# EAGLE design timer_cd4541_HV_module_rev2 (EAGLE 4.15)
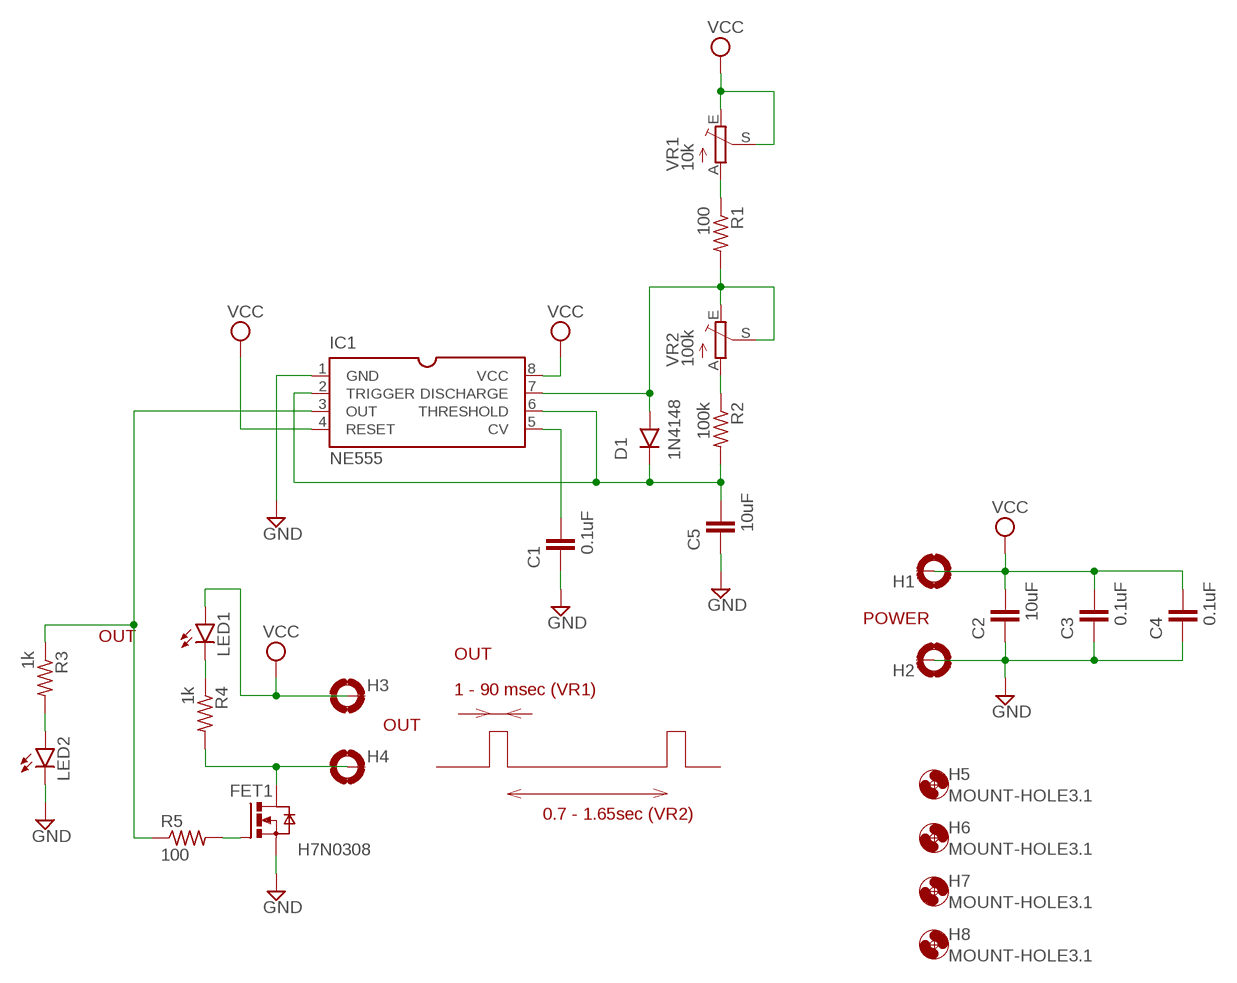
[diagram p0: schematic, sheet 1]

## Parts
C1  0.1uF  C-EU025-024X044_OLMX  [C025-024X044_OLMX]
C2  10uF  C-EU050-024X044_OLMX  [C050-024X044_OLMX]
C3  0.1uF  C-EU025-024X044_OLMX  [C025-024X044_OLMX]
C4  0.1uF  C-EU025-024X044_OLMX  [C025-024X044_OLMX]
C5  10uF  C-EU050-024X044_OLMX  [C050-024X044_OLMX]
D1  1N4148  DIODE  [DIODE]
FET1  H7N0308  IRF512HV  [TO-220HV]
H1  MOUNT-PAD-ROUND3.0-NOLING  [3,0-PAD-NOLING]
H2  MOUNT-PAD-ROUND3.0-NOLING  [3,0-PAD-NOLING]
H3  MOUNT-PAD-ROUND3.0-NOLING  [3,0-PAD-NOLING]
H4  MOUNT-PAD-ROUND3.0-NOLING  [3,0-PAD-NOLING]
H5  MOUNT-HOLE3.1  [3.1-HOLL]
H6  MOUNT-HOLE3.1  [3.1-HOLL]
H7  MOUNT-HOLE3.1  [3.1-HOLL]
H8  MOUNT-HOLE3.1  [3.1-HOLL]
IC1  NE555  [DIL8]
LED1  LED5MM_OLMX  [LED5MM_OLMX]
LED2  LED5MM_OLMX  [LED5MM_OLMX]
R1  100  R-US_0204/5_OLMX  [0204/5_OLMX]
R2  100k  R-US_0204/5_OLMX  [0204/5_OLMX]
R3  1k  R-US_0204/5_OLMX  [0204/5_OLMX]
R4  1k  R-US_0204/5_OLMX  [0204/5_OLMX]
R5  100  R-US_0204/5_OLMX  [0204/5_OLMX]
VR1  10k  TRIM_EU-B25P_OLMX  [B25P_OLMX]
VR2  100k  TRIM_EU-B25P_OLMX  [B25P_OLMX]

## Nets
GND [power]: C1.1 C2.1 C3.1 C4.1 C5.1 FET1.3(S) H2.B3,0(MOUNT) IC1.1(GND) LED2.K(C)
N$1: R2.1 VR2.A
N$4: R1.1 VR1.A
N$7: LED1.K(C) R4.1
N$8: C5.2 D1.K IC1.2(TRIGGER) IC1.6(THRESHOLD) R2.2
N$9: LED2.A R3.2
N$14: D1.A IC1.7(DISCHARGE) R1.2 VR2.E VR2.S
N$15: IC1.3(OUT) R3.1 R5.1
N$16: C1.2 IC1.5(CV)
N$19: FET1.1(G) R5.2
OUT-: FET1.2(D) H4.B3,0(MOUNT) R4.2
VCC [power]: C2.2 C3.2 C4.2 H1.B3,0(MOUNT) H3.B3,0(MOUNT) IC1.4(RESET) IC1.8(VCC) LED1.A VR1.E VR1.S

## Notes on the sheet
- POWER
- OUT
- OUT
- 1 - 90 msec (VR1)
- OUT
- 0.7 - 1.65sec (VR2)

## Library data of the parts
C1-C5 = rcl:C-EU: CAPACITOR, European symbol
D1 = 001mylib:DIODE
FET1 = transistor-power:IRF512: N-CHANNEL MOS FET
H1-H4 = holes:MOUNT-PAD-ROUND: MOUNTING PAD, round
H5-H8 = holes:MOUNT-HOLE: MOUNTING HOLE with drill center marker
IC1 = 001mylib:NE555
LED1 LED2 = led:LED: LED
R1-R5 = rcl:R-US_: RESISTOR, American symbol
VR1 VR2 = pot:TRIM_EU-: POTENTIOMETER

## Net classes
0 default: width 0.508 mm, drill 0.406 mm
1 power: width 0.635 mm, drill 0.508 mm

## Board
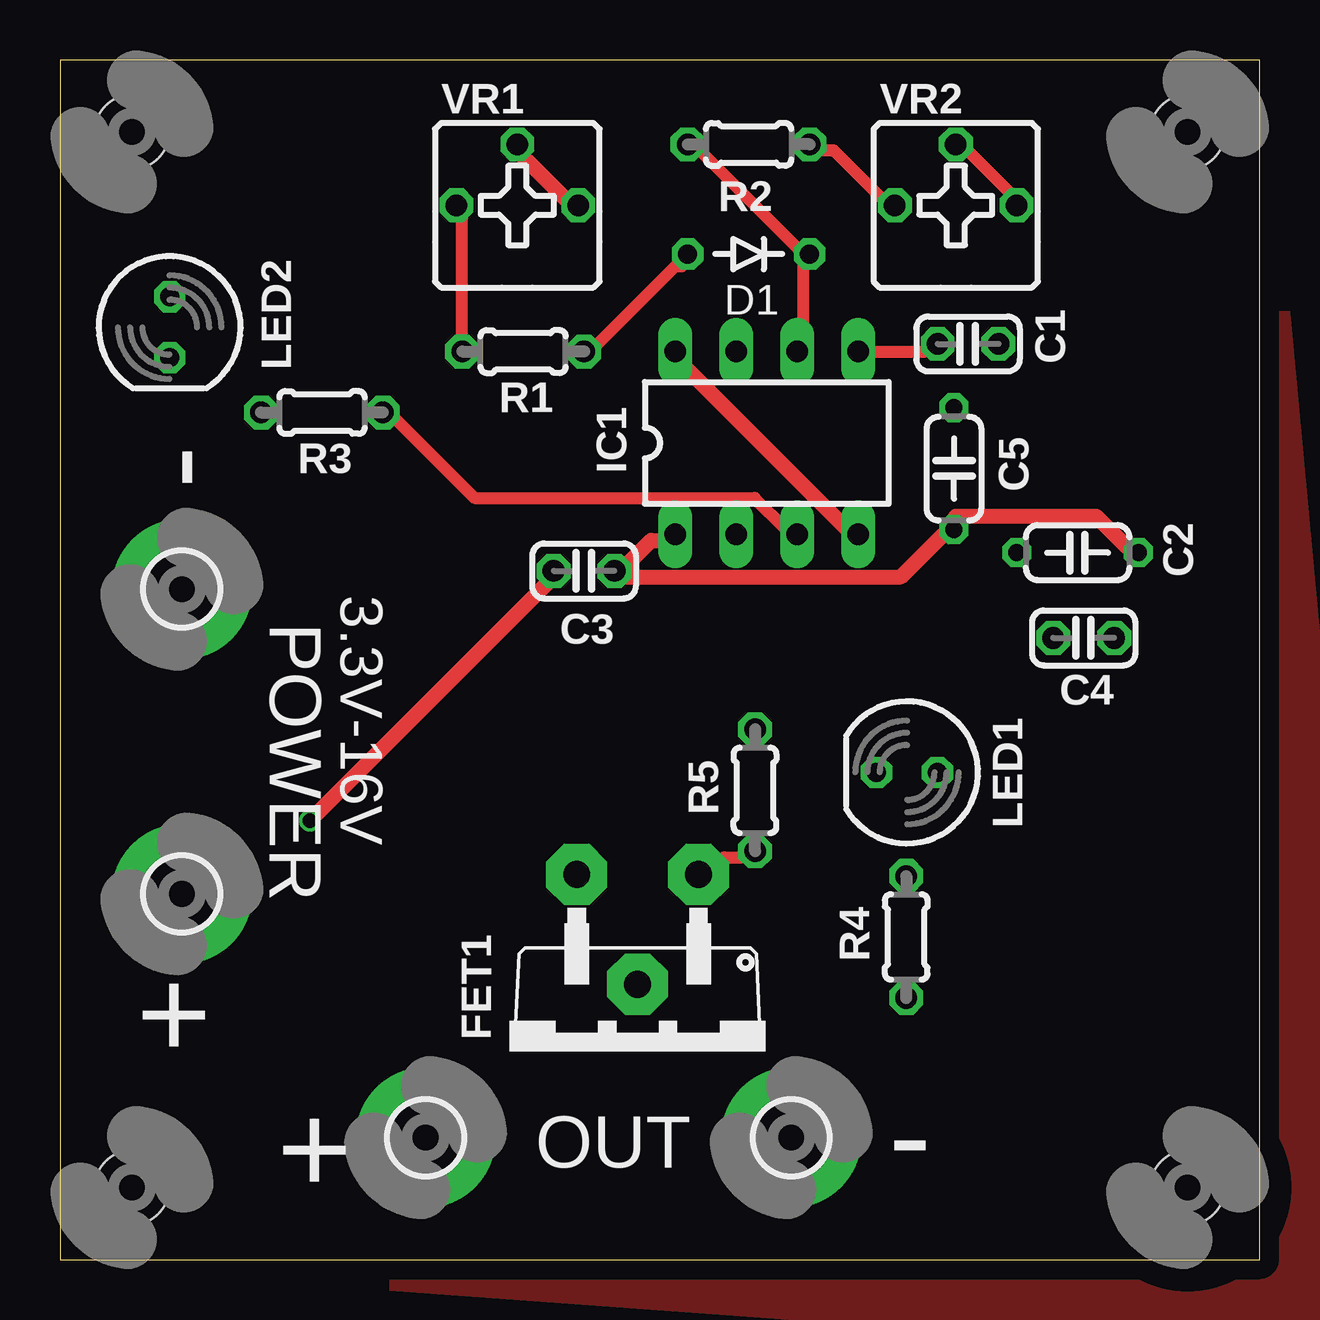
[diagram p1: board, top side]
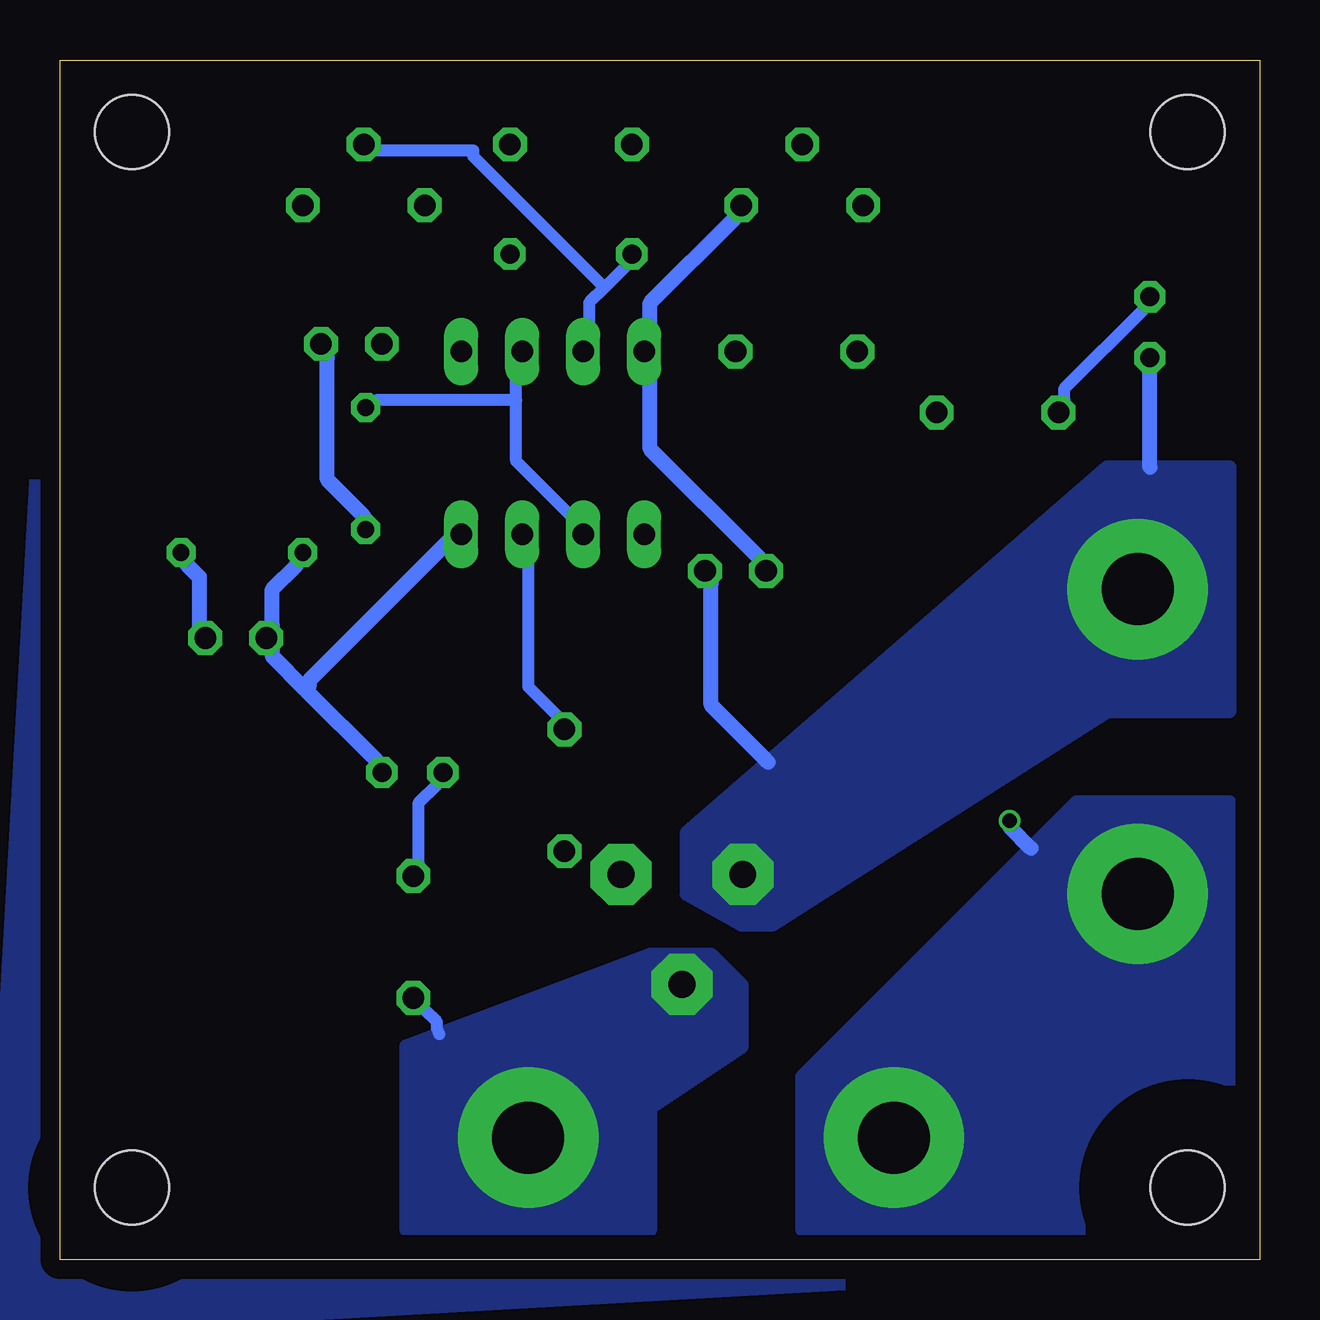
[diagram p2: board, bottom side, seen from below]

Size 50 x 50 mm. Coordinates in mm from the lower left corner, seen from the top.
Outline: 0,0 50,0 50,50 0,50 0,0
Copper layers (1*16): Top 0.035mm / dielectric 1.5mm / Bottom 0.035mm
Design rules "FUSION_IIZUKA_STANDARD": minimum track width 6mil, minimum drill 0.6mm, track to track 8mil, track to pad 8mil, pad to pad 8mil, via to via 8mil, smd to smd 0mil, copper to edge 30mil, drill to drill 10mil, minimum pad ring 10mil, minimum via ring 6mil, stop-mask expansion 2mil, vias tented up to drill 100mil, thermal gap 40mil
bKeepout: 5 lines
tRestrict: area 26.7,1 to 34.3,8.9; area 1,24.1 to 8.9,31.8

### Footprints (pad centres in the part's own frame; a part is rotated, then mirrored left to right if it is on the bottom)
C025-024X044_OLMX = drill 0.9 octagon: 1 -1.27,0; 2 1.27,0
C050-024X044_OLMX = drill 0.7 octagon: 1 -2.54,0; 2 2.54,0
DIODE = drill 0.8 octagon: A 2.54,0; K -2.54,0
TO-220HV = drill 1.118 pad 2.54 octagon: 1 -2.54,-1.016; 2 0,3.556; 3 2.54,-1.016
3,0-PAD-NOLING = drill 3 pad 5.842 round: B3,0 0,0
3.1-HOLL = hole 3.1: 0,0
DIL8 = drill 0.9 long: 1 -3.81,-3.81; 2 -1.27,-3.81; 3 1.27,-3.81; 4 3.81,-3.81; 5 3.81,3.81; 6 1.27,3.81; 7 -1.27,3.81; 8 -3.81,3.81
LED5MM_OLMX = drill 0.8 octagon: A -1.27,0; K 1.27,0
0204/5_OLMX = drill 0.9 octagon: 1 -2.54,0; 2 2.54,0
B25P_OLMX = drill 0.9 octagon: A -2.54,0; E 2.54,0; S 0,2.54

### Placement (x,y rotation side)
C1  37.85,38.16 180 top
C2  42.42,29.46 180 top
C3  21.84,28.7 180 top
C4  42.67,25.91 180 top
C5  37.26,32.97 90 top
D1  28.7,41.91 180 top
FET1  24.08,15.03 180 top
H1  5.08,15.24 0 top
H2  5.08,27.94 0 top
H3  15.24,5.08 0 top
H4  30.48,5.08 0 top
H5  3,3 0 top
H6  47,3 0 top
H7  3,47 0 top
H8  47,47 0 top
IC1  29.46,34.04 0 top
LED1  35.31,20.3 180 top
LED2  4.57,38.86 270 top
R1  19.3,37.85 0 top
R2  28.7,46.48 180 top
R3  10.92,35.31 180 top
R4  35.27,13.45 270 top
R5  28.97,19.56 270 top
VR1  19.06,43.94 0 top
VR2  37.34,43.94 0 top

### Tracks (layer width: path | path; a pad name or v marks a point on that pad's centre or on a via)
GND
  Top 0.635: C2.1 44.45,29.72 43.18,30.99 37.34,30.99 C5.1 36.83,30.23 35.05,28.45 23.62,28.45 C3.1 23.62,28.96 24.64,29.97 25.15,29.97 IC1.1
  Bottom 0.635: C2.1 44.7,28.96 44.2,28.45 44.2,26.42 C4.1 | C5.1 37.34,30.99 38.86,32.51 38.86,37.59 C1.1 | 4.57,33.02 LED2.K | 20.48,20.72 20.57,20.83 22.86,23.11 22.86,28.19 C3.1
  pour Bottom (isolate 0.813, rank 2): 53,-3 50,50 50,0 0,0
  pour Bottom (isolate 0.813, no thermals): 1.27,33.02 1.27,22.86 6.35,22.86 20.32,13.97 21.59,13.97 23.86,15.24 23.86,17.78 6.35,33.02
N$1
  Top 0.508: VR2.A 34.29,44.2 32.26,46.23 31.75,46.23 R2.1
N$4
  Top 0.508: R1.1 16.76,43.43 VR1.A
N$7
  Bottom 0.508: LED1.K 34.29,19.81 35.05,19.05 35.05,16.51 R4.1
N$8
  Top 0.508: IC1.6 30.99,38.35 30.99,41.4 D1.K 30.73,42.16 26.67,46.23 R2.2
  Bottom 0.508: 30.99,35.81 36.83,35.81 C5.2 | 30.99,35.81 30.99,37.34 IC1.6 | 30.99,35.81 30.99,33.27 28.45,30.73 IC1.2
N$9
  Bottom 0.508: LED2.A 4.83,39.62 8.13,36.32 8.13,35.81 R3.2
N$14
  Top 0.508: VR2.S 37.85,46.23 39.62,44.45 VR2.E | R1.2 22.35,38.1 25.65,41.4 25.91,41.4 D1.A
  Bottom 0.508: 27.3,40.51 27.94,39.88 27.94,38.35 IC1.7 | 27.3,40.51 26.42,41.4 D1.A | VR2.S 36.83,46.23 32.77,46.23 32.77,45.97 27.3,40.51
N$15
  Top 0.508: R3.1 13.97,35.05 17.27,31.75 28.96,31.75 30.23,30.48 IC1.3
  Bottom 0.508: R5.1 29.21,22.61 30.48,23.88 30.48,29.72 IC1.3
N$16
  Top 0.508: IC1.5 36.07,37.85 C1.2
N$19
  Top 0.508: R5.2 28.45,16.76 27.69,16.76 FET1.1
OUT-
  Bottom 0.508: R4.2 34.8,10.41 34.29,9.91 34.29,9.65 34.2,9.4
  pour Bottom (isolate 1.016, no thermals): 25.4,1.27 35.56,1.27 35.56,8.89 25.4,12.7 22.86,12.7 21.59,11.43 21.59,8.89 25.4,6.35
VCC  (via drill 0.6)
  Top 0.635: VR1.E 21.08,44.2 19.3,45.97 VR1.S | IC1.4 32.77,30.48 25.91,37.34 IC1.8 | v10.41,18.29 20.32,28.19 C3.2
  Bottom 0.635: C2.2 40.13,28.96 41.15,27.94 41.15,26.42 C4.2 41.15,25.4 41.15,25.15 39.75,23.75 | 39.75,23.75 36.83,20.83 LED1.A | IC1.4 33.78,29.97 39.62,24.13 39.62,23.88 39.75,23.75 | C3.2 20.83,29.21 25.4,33.78 25.4,37.34 IC1.8 25.4,38.35 25.4,39.88 21.84,43.43 VR1.E | v10.41,18.29 10.41,18.03 9.53,17.14
  pour Top (isolate 0.813, rank 2): 55,-4 50,50 50,0 0,0
  pour Bottom (isolate 1.016, no thermals): 1.27,19.05 1.27,1.27 19.05,1.27 19.05,7.62 7.62,19.05

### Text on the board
tPlace: - | 3.3V-16V | POWER | + | OUT | + | -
